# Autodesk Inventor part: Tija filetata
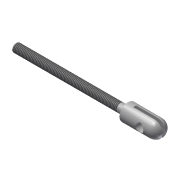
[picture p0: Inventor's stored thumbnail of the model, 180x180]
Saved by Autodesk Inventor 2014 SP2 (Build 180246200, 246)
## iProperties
Created: 2015-04
Part Number: Tija filetata
Material: Steel
Document SubType Name: Modeling
Designer: SFC
Density: 7.85 g/cm^3
Appearance: Steel
Mass: 24.3867 g
Surface Area: 22.8192 cm^2
Volume: 3.10658 cm^3
Author: SFC
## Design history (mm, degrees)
sketch "Sketch1"
  geometry: L1 (-40, 3)-(0, 3); L2 (0, 3)-(0, 6); L3 (0, 6)-(20, 6); L4 (-40, 3)-(-40, 0); L5 (-40, 0)-(26, 0); A1 r 6 centre (20, 0) between (26, 0) and (20, 6); 1 further point
  constraints: 10 end point, 3 perpendicular, 3 point on line, 2 point on circle, 1 centre point, 1 horizontal, 1 parallel, 1 tangent
  dimensions: "d0" = 6 diameter of L1 L5; "d1" = 12 diameter of L3 L5; "d2" = 40 distance between parallel lines of L2 L4; "d3" = 60 distance from line of A1.centre L4
revolve "Revolution1" sketch "Sketch1" stored, may be unused: angle "d5" = 90 deg
sketch "Sketch2"
  geometry: L1 (25.916, 1)-(5, 1); L2 (5, 1)-(5, -1); L3 (5, -1)-(25.916, -1); A1 r 6 centre (20, 0) between (20, -6) and (20, 6) reference; A2 r 6 centre (20, 0) between (25.916, -1) and (25.916, 1); 2 further points
  constraints: 6 end point, 4 point on circle, 1 centre point, 1 horizontal, 1 horizontal alignment, 1 midpoint, 1 parallel, 1 perpendicular
  dimensions: "d6" = 2 distance between parallel lines of L3 L1; "d7" = 15 distance from line of A1.centre L2
extrude "Extrusion1" cut sketch "Sketch2" stored distance "d8" = 10; taper "d9" = 0 deg
sketch "Sketch3"
  geometry: L1 (-5, -5.916)-(-5, 5.916) reference; C1 r 3 at (-20, 0); 1 further point
  constraints: 1 centre point
  dimensions: "d10" = 15 distance from line of L1 C1.centre; "d11" = 6 diameter of C1
extrude "Extrusion2" cut sketch "Sketch3" stored distance "d12" = 10; taper "d13" = 0 deg
thread "Thread1" dims "d14" = 35, "d15" = 0
chamfer "Chamfer1" distance "d16" = 0.5; stored, may be unused: second distance "d17" = 2, angle "d18" = 45 deg
body "Solid1"
